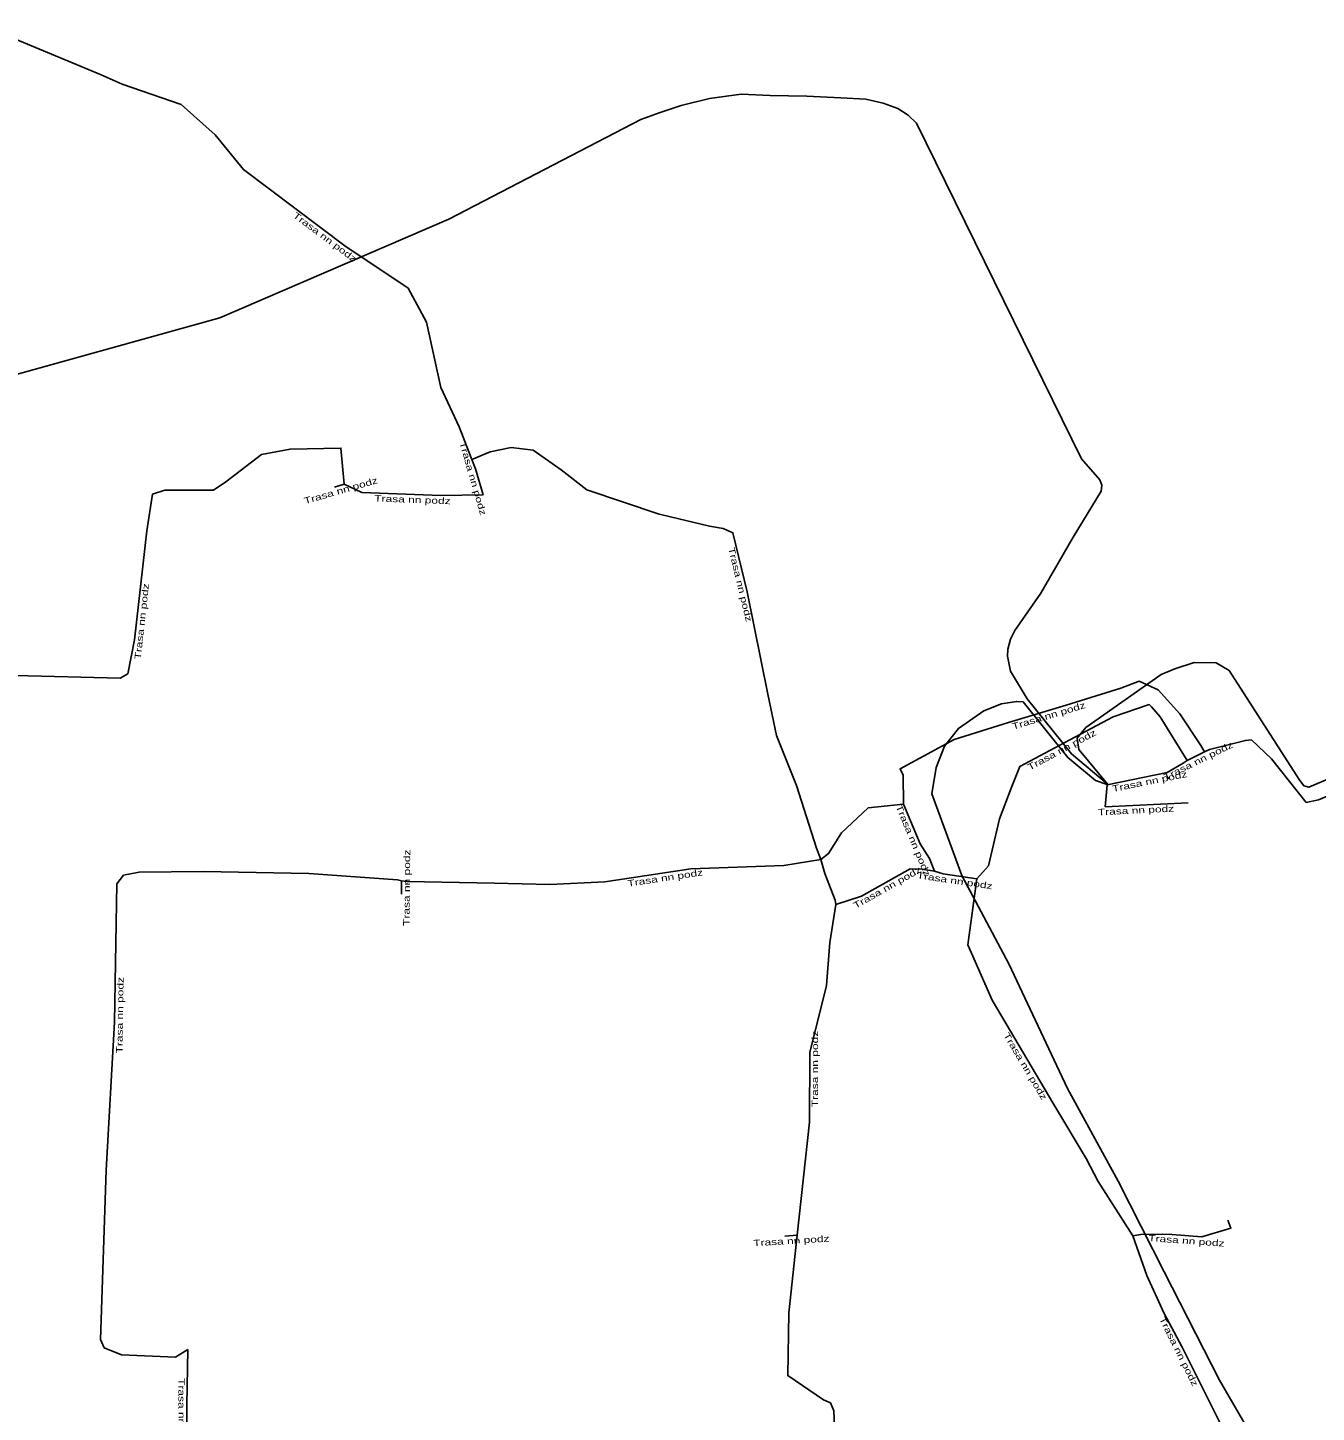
# Model space of a CAD drawing. Extents: x -750058 to -747751, y -1025655 to -1024104.
# Drawn here: x -748607.9 to -748506.9, y -1025066.9 to -1024958.3 of the extents above; entities that cross this region are included whole.
import ezdxf
from ezdxf.enums import TextEntityAlignment as Align

# ---------------------------------------------------------------- set-up
doc = ezdxf.new("R2010")
doc.units = 0
doc.header["$LTSCALE"] = 0.2
doc.layers.add('11', color=7, linetype='Continuous', lineweight=25)
doc.layers.add('21', color=7, linetype='Continuous', lineweight=25)
doc.layers.add('20', color=7, linetype='Continuous')

msp = doc.modelspace()

# ---------------------------------------------------------------- linework, layer by layer
at = {"layer": '11'}
for p, q in [((-748583.12, -1024994.13), (-748583.88, -1024994.35)), ((-748578.62, -1025025.23), (-748578.63, -1025026.28)), ((-748547.61, -1025053.01), (-748548.57, -1025053.07))]:
    msp.add_line(p, q, dxfattribs=at)
for points in [[(-748602.18, -1024962.03), (-748608.89, -1024959.24), (-748619.76, -1024958.34), (-748620.54, -1024958.43), (-748620.6, -1024960.64)], [(-748573.12, -1024992.18), (-748573.35, -1024991.59), (-748574.1, -1024989.63), (-748575.55, -1024986.55), (-748576.68, -1024981.42), (-748578.11, -1024978.75), (-748580.73, -1024977.01), (-748582.96, -1024975.51), (-748591.02, -1024969.47), (-748593.24, -1024966.74), (-748595.9, -1024964.37), (-748600.54, -1024962.77), (-748602.18, -1024962.03)], [(-748515.66, -1025015.12), (-748515.27, -1025014.92), (-748512.47, -1025014.21), (-748511.99, -1025014.18), (-748510.41, -1025015.66), (-748508.41, -1025018.19), (-748507.69, -1025019.08), (-748506.74, -1025018.88), (-748503.98, -1025017.73), (-748502.73, -1025016.06), (-748496.36, -1025012.79), (-748494.43, -1025012.42), (-748493.34, -1025011.87), (-748472.7, -1024998.04), (-748469.8, -1024996.17), (-748464.77, -1024992.63), (-748468.8, -1024983.48)], [(-748544.58, -1025027.09), (-748544.63, -1025026.74), (-748545.43, -1025024.65), (-748545.74, -1025023.54), (-748546.08, -1025022.66), (-748547.66, -1025017.74), (-748549.23, -1025013.82), (-748549.9, -1025010.58), (-748551.52, -1025002.56), (-748552.64, -1024997.94), (-748553.42, -1024997.59), (-748554.48, -1024997.43), (-748558.19, -1024996.54), (-748558.42, -1024996.48), (-748564.09, -1024994.58), (-748566.11, -1024992.99), (-748568.32, -1024991.46), (-748570.02, -1024991.26), (-748571.69, -1024991.59), (-748573.12, -1024992.18)], [(-748624.2, -1025007.33), (-748623.51, -1025007.77), (-748619.62, -1025008.46), (-748614.71, -1025008.5), (-748608.93, -1025009.13), (-748600.68, -1025009.33), (-748600.09, -1025008.99), (-748599.56, -1025006.34), (-748598.61, -1024997.78), (-748598.16, -1024994.92), (-748597.19, -1024994.6), (-748593.36, -1024994.6), (-748592.41, -1024993.94), (-748589.6, -1024991.79), (-748587.36, -1024991.38), (-748583.38, -1024991.3), (-748583.12, -1024994.13)], [(-748572.24, -1024994.96), (-748572.83, -1024992.92), (-748573.12, -1024992.18)], [(-748583.12, -1024994.13), (-748581.73, -1024994.79), (-748575.55, -1024995.02), (-748572.24, -1024994.96)], [(-748539.26, -1025019.22), (-748539.3, -1025016.94), (-748539.54, -1025016.43), (-748535.31, -1025014.14), (-748531.03, -1025012.81), (-748526.52, -1025011.45), (-748522.23, -1025010.13), (-748520.79, -1025009.58), (-748519.31, -1025010.26), (-748517.61, -1025012.14), (-748515.95, -1025014.6), (-748515.66, -1025015.12)], [(-748517.03, -1025015.8), (-748519.14, -1025012.37), (-748519.84, -1025011.57), (-748520.01, -1025011.41), (-748522.82, -1025012.37), (-748526.23, -1025014.16), (-748530.15, -1025016.25), (-748530.84, -1025017.96), (-748531.75, -1025020.35), (-748532.61, -1025024.04), (-748533.53, -1025025.06)], [(-748515.66, -1025015.12), (-748516.34, -1025015.46), (-748517.03, -1025015.8)], [(-748523.294, -1025017.684), (-748518.61, -1025016.74), (-748517.34, -1025015.99), (-748517.03, -1025015.8)], [(-748523.294, -1025017.684), (-748523.448, -1025019.411), (-748516.946, -1025019.094)], [(-748578.62, -1025025.23), (-748578.21, -1025025.27), (-748571.33, -1025025.4), (-748567, -1025025.5), (-748562.68, -1025025.3), (-748555.95, -1025024.28), (-748548.65, -1025024.01), (-748545.74, -1025023.54), (-748545.14, -1025023.09), (-748544.13, -1025021.46), (-748542.03, -1025019.49), (-748539.26, -1025019.22)], [(-748536.84, -1025024.47), (-748537.23, -1025023.48), (-748537.97, -1025022.32), (-748539.26, -1025019.22)], [(-748595.38, -1025061.97), (-748596.35, -1025062.56), (-748600.58, -1025062.37), (-748601.94, -1025061.83), (-748602.23, -1025061.19), (-748601.78, -1025047.91), (-748601.12, -1025036.31), (-748600.95, -1025025.45), (-748600.42, -1025024.78), (-748599.21, -1025024.53), (-748594.16, -1025024.48), (-748585.89, -1025024.65), (-748578.94, -1025025.15), (-748578.62, -1025025.23)], [(-748544.58, -1025027.09), (-748542.57, -1025026.42), (-748538.75, -1025024.27), (-748537.8, -1025024.31), (-748536.84, -1025024.47)], [(-748536.84, -1025024.47), (-748536.17, -1025024.67), (-748533.53, -1025025.06)], [(-748533.53, -1025025.06), (-748534.24, -1025030.23), (-748532.32, -1025034.58), (-748527.48, -1025042.76), (-748524.94, -1025046.98), (-748524.02, -1025048.78), (-748521.29, -1025053.06)], [(-748547.61, -1025053.01), (-748546.63, -1025044.13), (-748546.62, -1025038.69), (-748545.31, -1025033.43), (-748545.06, -1025030.06), (-748544.58, -1025027.09)], [(-748521.29, -1025053.06), (-748520.51, -1025052.93), (-748518.24, -1025052.95), (-748515.89, -1025053.12), (-748513.6, -1025052.46), (-748513.85, -1025051.82)], [(-748547.05, -1025103.34), (-748547.11, -1025100.14), (-748546.91, -1025096.21), (-748546.61, -1025090.51), (-748546.57, -1025088.17), (-748546.05, -1025080.02), (-748545.37, -1025075.94), (-748544.53, -1025071.57), (-748544.73, -1025066.76), (-748545, -1025066.14), (-748545.55, -1025065.9), (-748548.35, -1025064.01), (-748548.27, -1025059.09), (-748547.61, -1025053.01)], [(-748521.29, -1025053.06), (-748520.2, -1025056.16), (-748518.85, -1025059.1), (-748517.41, -1025061.79), (-748514.53, -1025067.58), (-748513.15, -1025070.73)], [(-748595.4, -1025072.42), (-748595.43, -1025071.78), (-748595.47, -1025066.3), (-748595.38, -1025061.97)]]:
    msp.add_lwpolyline(points, dxfattribs=at)
at = {"layer": '21'}
for points in [[(-748523.294, -1025017.684), (-748523.316, -1025017.623), (-748526.1, -1025015.276), (-748529.573, -1025010.953), (-748530.891, -1025008.774), (-748531.115, -1025007.622), (-748531.093, -1025007.068), (-748530.891, -1025006.281), (-748530.544, -1025005.591), (-748528.495, -1025002.679), (-748525.978, -1024998.273), (-748523.786, -1024994.666), (-748523.724, -1024994.198), (-748523.875, -1024993.786), (-748525.311, -1024992.143), (-748538.257, -1024965.814), (-748538.904, -1024965.195), (-748539.709, -1024964.672), (-748540.871, -1024964.252), (-748542.234, -1024963.938), (-748544.177, -1024963.836), (-748546.861, -1024963.708), (-748549.722, -1024963.645), (-748551.998, -1024963.542), (-748554.482, -1024963.896), (-748556.695, -1024964.441), (-748558.439, -1024965.007), (-748559.853, -1024965.536), (-748574.931, -1024973.353), (-748592.88, -1024981.08), (-748624.557, -1024989.9)], [(-748523.294, -1025017.684), (-748523.254, -1025017.662), (-748525.524, -1025014.92), (-748525.662, -1025014.048), (-748524.973, -1025013.208), (-748519.071, -1025009.046), (-748517.998, -1025008.6), (-748516.489, -1025008.102), (-748514.758, -1025008.137), (-748513.746, -1025008.723), (-748508.246, -1025017.27), (-748507.88, -1025017.762), (-748507.481, -1025017.891), (-748503.273, -1025016.113)], [(-748523.294, -1025017.684), (-748523.303, -1025017.675), (-748524.216, -1025017.359), (-748526.387, -1025015.557), (-748529.901, -1025011.183), (-748530.419, -1025011.152), (-748531.582, -1025011.347), (-748532.984, -1025011.907), (-748534.969, -1025013.279), (-748536.056, -1025014.675), (-748536.712, -1025016.324), (-748537.041, -1025018.396), (-748534.689, -1025024.81), (-748531.008, -1025031.716), (-748526.417, -1025041.512), (-748522.439, -1025048.778), (-748518.836, -1025055.862), (-748514.485, -1025064.363), (-748509.288, -1025073.32)]]:
    msp.add_lwpolyline(points, dxfattribs=at)

# ---------------------------------------------------------------- texts
at = {"layer": '20', "width": 1.4}
for rotation, p in [(323.153, (-748584.7934, -1024974.9471)), (286.131, (-748573.2696, -1024993.738)), (16.144, (-748583.319, -1024994.8638)), (357.869, (-748577.7788, -1024995.5869)), (283.627, (-748552.3125, -1025002.0486)), (83.667, (-748598.7473, -1025004.9081)), (16.781, (-748527.8117, -1025012.5175)), (28.065, (-748526.7451, -1025015.1711)), (26.232, (-748516.056, -1025016.0444)), (11.399, (-748519.9229, -1025017.6678)), (292.594, (-748538.7462, -1025022.1455)), (2.791, (-748521.0307, -1025019.9429)), (89.454, (-748577.9741, -1025025.7609)), (8.618, (-748557.915, -1025025.2349)), (29.372, (-748540.4251, -1025025.9579)), (351.597, (-748535.29, -1025025.4564)), (89.103, (-748600.4608, -1025035.7554)), (89.895, (-748545.9712, -1025039.973)), (300.612, (-748529.9364, -1025039.8822)), (3.576, (-748548.0491, -1025053.6879)), (355.862, (-748517.1065, -1025053.6828)), (296.446, (-748517.9172, -1025062.2272)), (270.418, (-748596.1121, -1025067.1997))]:
    msp.add_text('Trasa nn podz', height=0.5, rotation=rotation, dxfattribs=at).set_placement(p, align=Align.CENTER)

doc.saveas('drawing.dxf')
